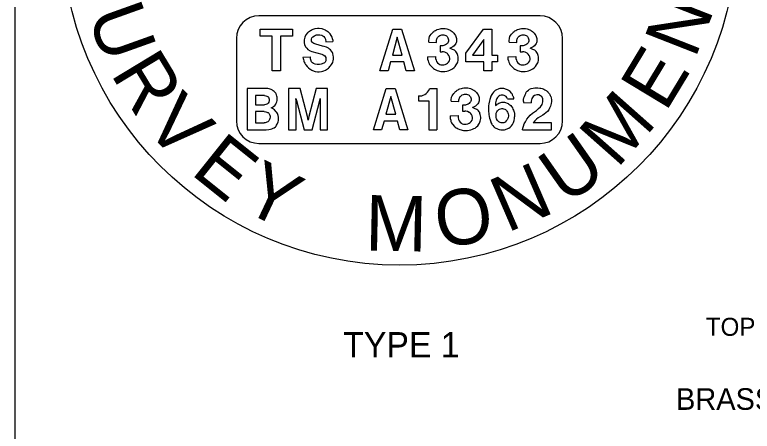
# Model space of a CAD drawing. Extents: x 99862 to 103151, y 100000 to 102076.
# Drawn here: x 99862 to 100680, y 101141 to 101603 of the extents above; entities that cross this region are included whole.
import ezdxf

# ---------------------------------------------------------------- set-up
doc = ezdxf.new("R2010")
doc.units = 0
for name, color, linetype in [('Level 1', 7, 'Continuous'), ('Level 10', 7, 'Continuous'), ('Level 13', 7, 'Continuous'), ('Level 20', 7, 'Continuous'), ('Level 6', 7, 'Continuous')]:
    doc.layers.add(name, color=color, linetype=linetype)

msp = doc.modelspace()

# ---------------------------------------------------------------- linework, layer by layer
at = {"layer": 'Level 1'}
msp.add_lwpolyline([(99862, 99999.5), (103151, 99999.5), (103151, 102075.5), (99862, 102075.5)], close=True, dxfattribs=at)
at = {"layer": 'Level 13'}
for p, q in [((100469.61, 101484.97), (100469.61, 101576.53)), ((100132.83, 101459.97), (100444.61, 101459.97))]:
    msp.add_line(p, q, dxfattribs=at)
for points in [[(100444.61, 101601.53), (100132.83, 101601.53)], [(100107.83, 101576.53), (100107.83, 101484.97)]]:
    msp.add_lwpolyline(points, dxfattribs=at)
for centre, start, end in [((100132.83, 101576.53), 90, 180), ((100444.61, 101576.53), 0, 90), ((100132.83, 101484.97), 180, 270), ((100444.61, 101484.97), 270, 0)]:
    msp.add_arc(centre, 25, start, end, dxfattribs=at)
at = {"layer": 'Level 20'}
for points in [[(100134.35, 101586.59), (100169.91, 101586.59), (100169.91, 101578.98), (100156.7, 101578.98), (100156.7, 101540.59), (100147.56, 101540.59), (100147.56, 101578.98), (100134.35, 101578.98), (100134.35, 101586.59)], [(100187.89, 101583.69), (100188.9, 101584.42), (100189.92, 101585.14), (100190.6, 101585.51), (100191.95, 101586.23), (100193.98, 101586.96), (100195.33, 101587.31), (100197.71, 101587.67), (100198.38, 101587.67), (100199.74, 101587.67), (100202.45, 101587.31), (100203.47, 101586.96), (100204.48, 101586.59), (100206.17, 101585.87), (100207.53, 101585.14), (100208.2, 101584.78), (100209.22, 101584.06)], [(100266.96, 101540.59), (100281.18, 101586.59), (100291, 101586.59), (100305.22, 101540.59), (100296.08, 101540.59), (100293.71, 101550.37), (100278.81, 101550.37), (100276.11, 101540.59), (100266.96, 101540.59)], [(100321.14, 101572.46), (100321.14, 101573.55), (100321.14, 101574.64), (100321.48, 101576.09), (100321.48, 101576.81), (100322.16, 101578.62), (100322.84, 101579.71), (100323.85, 101581.16), (100324.53, 101581.88), (100325.21, 101582.61), (100325.88, 101583.33), (100326.9, 101584.06), (100327.58, 101584.78), (100328.59, 101585.14), (100329.6, 101585.87), (100330.62, 101586.23), (100332.31, 101586.59), (100333.67, 101586.96), (100335.02, 101587.31), (100336.38, 101587.31), (100338.07, 101587.31), (100339.43, 101587.31), (100341.12, 101586.96), (100342.47, 101586.59), (100344.84, 101585.51), (100345.18, 101585.14), (100346.2, 101584.78), (100347.21, 101584.06), (100347.89, 101583.33), (100348.91, 101582.24), (100349.92, 101581.16), (100350.94, 101579.71), (100351.62, 101577.53), (100351.95, 101576.45), (100351.95, 101575), (100351.95, 101572.83), (100351.62, 101571.74), (100351.28, 101570.65), (100350.6, 101569.57), (100350.26, 101569.2), (100349.25, 101568.12), (100347.89, 101567.03), (100346.53, 101566.31), (100344.51, 101565.58)], [(100362.45, 101550.37), (100362.45, 101560.15), (100382.08, 101586.59), (100391.23, 101586.59), (100391.23, 101557.98), (100397.32, 101557.98), (100397.32, 101550.37), (100391.23, 101550.37), (100391.23, 101540.59), (100382.43, 101540.59), (100382.43, 101550.37), (100362.45, 101550.37)], [(100410.24, 101572.46), (100410.24, 101573.55), (100410.24, 101574.64), (100410.58, 101576.09), (100410.58, 101576.81), (100411.25, 101578.62), (100411.93, 101579.71), (100412.95, 101581.16), (100413.62, 101581.88), (100414.3, 101582.61), (100414.98, 101583.33), (100416, 101584.06), (100416.67, 101584.78), (100417.69, 101585.14), (100418.7, 101585.87), (100419.72, 101586.23), (100421.41, 101586.59), (100422.76, 101586.96), (100424.12, 101587.31), (100425.47, 101587.31), (100427.16, 101587.31), (100428.52, 101587.31), (100430.21, 101586.96), (100431.57, 101586.59), (100433.94, 101585.51), (100434.28, 101585.14), (100435.3, 101584.78), (100436.31, 101584.06), (100436.98, 101583.33), (100438, 101582.24), (100439.02, 101581.16), (100440.03, 101579.71), (100440.71, 101577.53), (100441.05, 101576.45), (100441.05, 101575), (100441.05, 101572.83), (100440.71, 101571.74), (100440.37, 101570.65), (100439.69, 101569.57), (100439.36, 101569.2), (100438.34, 101568.12), (100436.98, 101567.03), (100435.63, 101566.31), (100433.6, 101565.58)], [(100187.89, 101583.69), (100186.53, 101582.61), (100184.84, 101580.43), (100183.82, 101577.9), (100183.15, 101575), (100183.15, 101571.74), (100183.49, 101569.57), (100184.51, 101567.03), (100185.86, 101565.58), (100187.21, 101564.14), (100189.58, 101562.69), (100191.61, 101561.96), (100202.45, 101559.06), (100204.14, 101558.33), (100205.83, 101557.25)], [(100191.27, 101573.55), (100191.27, 101575.73), (100191.61, 101577.17), (100192.63, 101578.26), (100194.32, 101579.35), (100195.68, 101580.07), (100196.69, 101580.43), (100198.38, 101580.43), (100200.42, 101580.43), (100202.45, 101580.07), (100203.8, 101579.35), (100204.82, 101578.62), (100205.83, 101577.17), (100206.51, 101575.73), (100206.85, 101572.83)], [(100214.64, 101575), (100213.62, 101578.62), (100212.95, 101579.71), (100211.93, 101581.52), (100210.91, 101582.61), (100209.22, 101584.06)], [(100329.6, 101572.1), (100329.6, 101573.91), (100329.95, 101575), (100330.29, 101575.73), (100330.62, 101576.81), (100330.96, 101577.53), (100331.64, 101578.26), (100332.31, 101578.98), (100333.33, 101579.71), (100334.69, 101580.07), (100335.7, 101580.43), (100337.06, 101580.43), (100338.07, 101580.43), (100339.09, 101580.07), (100340.1, 101579.71), (100340.78, 101579.35), (100341.46, 101578.62), (100342.13, 101577.9), (100342.47, 101577.17), (100342.81, 101576.09), (100343.15, 101575), (100343.15, 101573.55), (100342.81, 101572.46), (100342.47, 101571.74), (100341.8, 101571.01), (100340.78, 101569.93), (100339.77, 101569.2), (100338.75, 101568.85), (100337.73, 101568.48), (100336.72, 101568.12), (100336.04, 101568.12)], [(100418.7, 101572.1), (100418.7, 101573.91), (100419.04, 101575), (100419.38, 101575.73), (100419.72, 101576.81), (100420.05, 101577.53), (100420.73, 101578.26), (100421.41, 101578.98), (100422.43, 101579.71), (100423.78, 101580.07), (100424.8, 101580.43), (100426.15, 101580.43), (100427.16, 101580.43), (100428.18, 101580.07), (100429.2, 101579.71), (100429.87, 101579.35), (100430.55, 101578.62), (100431.23, 101577.9), (100431.57, 101577.17), (100431.9, 101576.09), (100432.25, 101575), (100432.25, 101573.55), (100431.9, 101572.46), (100431.57, 101571.74), (100430.89, 101571.01), (100429.87, 101569.93), (100428.86, 101569.2), (100427.84, 101568.85), (100426.83, 101568.48), (100425.81, 101568.12), (100425.14, 101568.12)], [(100214.64, 101549.65), (100214.98, 101550.01), (100215.31, 101551.46), (100215.65, 101553.27), (100215.65, 101555.08), (100215.65, 101556.17), (100215.31, 101557.62), (100214.64, 101559.79), (100214.3, 101560.87), (100213.29, 101562.32), (100212.27, 101563.77), (100211.25, 101564.49), (100209.9, 101565.58), (100207.87, 101566.67), (100205.16, 101567.39), (100203.47, 101567.76), (100196.02, 101569.93), (100193.64, 101571.01), (100192.63, 101571.74), (100191.95, 101572.46), (100191.27, 101573.55)], [(100206.85, 101572.83), (100214.98, 101573.19)], [(100214.64, 101575), (100214.98, 101573.19)], [(100286.26, 101577.9), (100280.84, 101557.98), (100291.68, 101557.98), (100286.26, 101577.9)], [(100321.14, 101572.46), (100329.6, 101572.1)], [(100382.43, 101575.36), (100369.56, 101557.98), (100382.43, 101557.98), (100382.43, 101575.36)], [(100410.24, 101572.46), (100418.7, 101572.1)], [(100319.79, 101556.17), (100319.79, 101553.27), (100320.47, 101551.46), (100320.8, 101550.01), (100321.48, 101548.56), (100322.16, 101547.47), (100323.17, 101546.39), (100322.5, 101547.11), (100324.86, 101544.57), (100325.55, 101543.85), (100326.56, 101543.12), (100327.58, 101542.4), (100328.93, 101541.67), (100330.62, 101540.96), (100334.69, 101539.87), (100335.7, 101539.87), (100337.39, 101539.87), (100339.09, 101539.87), (100341.12, 101540.23), (100342.81, 101540.59), (100344.51, 101541.31), (100346.2, 101542.04), (100347.56, 101542.76), (100349.25, 101544.21), (100350.6, 101545.3), (100351.62, 101547.11), (100352.29, 101548.2), (100352.97, 101549.28), (100353.31, 101550.37), (100353.64, 101551.82), (100353.99, 101553.27), (100353.99, 101554.72), (100353.64, 101556.17), (100353.31, 101557.62), (100352.97, 101558.7), (100352.63, 101559.79), (100351.95, 101560.87), (100351.28, 101561.96), (100350.6, 101562.69), (100349.58, 101563.41), (100348.57, 101563.77), (100347.56, 101564.14), (100346.2, 101564.86), (100344.51, 101565.58)], [(100328.59, 101556.53), (100328.59, 101554.35), (100329.27, 101552.18), (100329.95, 101550.73), (100330.96, 101549.28), (100332.31, 101548.2), (100333.33, 101547.47), (100334.69, 101547.11), (100336.38, 101547.11), (100337.73, 101547.11), (100339.43, 101547.47), (100340.78, 101548.2), (100342.13, 101548.92), (100343.15, 101550.01), (100344.16, 101551.46), (100344.51, 101552.9), (100344.51, 101554.35), (100344.16, 101556.17), (100343.49, 101557.62), (100342.47, 101559.06), (100341.8, 101559.79), (100341.12, 101560.15), (100339.09, 101561.24), (100337.39, 101561.6), (100336.04, 101561.6)], [(100336.04, 101568.12), (100333.67, 101568.12), (100333.67, 101561.6), (100336.04, 101561.6)], [(100408.88, 101556.17), (100408.88, 101553.27), (100409.56, 101551.46), (100409.9, 101550.01), (100410.58, 101548.56), (100411.25, 101547.47), (100412.27, 101546.39), (100411.59, 101547.11), (100413.96, 101544.57), (100414.64, 101543.85), (100415.65, 101543.12), (100416.67, 101542.4), (100418.03, 101541.67), (100419.72, 101540.96), (100423.78, 101539.87), (100424.8, 101539.87), (100426.49, 101539.87), (100428.18, 101539.87), (100430.21, 101540.23), (100431.9, 101540.59), (100433.6, 101541.31), (100435.3, 101542.04), (100436.65, 101542.76), (100438.34, 101544.21), (100439.69, 101545.3), (100440.71, 101547.11), (100441.38, 101548.2), (100442.07, 101549.28), (100442.4, 101550.37), (100442.74, 101551.82), (100443.08, 101553.27), (100443.08, 101554.72), (100442.74, 101556.17), (100442.4, 101557.62), (100442.07, 101558.7), (100441.73, 101559.79), (100441.05, 101560.87), (100440.37, 101561.96), (100439.69, 101562.69), (100438.68, 101563.41), (100437.66, 101563.77), (100436.65, 101564.14), (100435.3, 101564.86), (100433.6, 101565.58)], [(100417.69, 101556.53), (100417.69, 101554.35), (100418.36, 101552.18), (100419.04, 101550.73), (100420.05, 101549.28), (100421.41, 101548.2), (100422.43, 101547.47), (100423.78, 101547.11), (100425.47, 101547.11), (100426.83, 101547.11), (100428.52, 101547.47), (100429.87, 101548.2), (100431.23, 101548.92), (100432.25, 101550.01), (100433.26, 101551.46), (100433.6, 101552.9), (100433.6, 101554.35), (100433.26, 101556.17), (100432.58, 101557.62), (100431.57, 101559.06), (100430.89, 101559.79), (100430.21, 101560.15), (100428.18, 101561.24), (100426.49, 101561.6), (100425.14, 101561.6)], [(100425.14, 101568.12), (100422.76, 101568.12), (100422.76, 101561.6), (100425.14, 101561.6)], [(100181.46, 101555.8), (100189.92, 101556.17)], [(100181.46, 101555.8), (100181.8, 101554.35), (100182.13, 101552.9), (100182.47, 101551.46), (100182.81, 101550.73), (100183.15, 101550.01), (100183.82, 101548.92), (100184.51, 101547.47), (100184.84, 101547.11), (100186.2, 101545.3), (100187.89, 101543.85), (100189.58, 101542.4), (100190.26, 101542.04), (100191.61, 101541.31), (100192.29, 101540.96), (100193.31, 101540.59), (100193.98, 101540.23), (100195.33, 101539.87), (100197.71, 101539.51), (100198.73, 101539.51), (100199.74, 101539.51), (100202.11, 101539.87), (100203.8, 101540.23), (100204.82, 101540.59), (100206.51, 101541.31), (100207.87, 101542.04), (100208.88, 101542.76), (100209.9, 101543.49), (100210.58, 101544.21), (100211.59, 101545.3), (100212.27, 101546.02), (100213.29, 101547.47), (100213.96, 101548.56), (100214.64, 101549.65)], [(100203.12, 101548.2), (100201.77, 101547.83), (100200.08, 101547.47), (100198.38, 101547.47), (100197.37, 101547.47), (100195.33, 101547.83), (100193.31, 101548.56), (100192.29, 101549.28), (100191.27, 101550.37), (100190.6, 101551.46), (100190.26, 101552.54), (100189.92, 101553.99), (100189.92, 101556.17)], [(100205.83, 101557.25), (100206.85, 101555.44), (100206.85, 101551.46), (100206.17, 101550.01), (100205.5, 101549.28), (100203.12, 101548.2)], [(100319.79, 101556.17), (100328.59, 101556.53)], [(100408.88, 101556.17), (100417.69, 101556.53)], [(100140.94, 101520.92), (100119.95, 101520.92), (100119.95, 101474.92), (100139.58, 101474.92)], [(100139.58, 101474.92), (100140.94, 101474.92), (100143.99, 101475.28), (100145.68, 101475.64), (100147.03, 101476), (100148.05, 101476.37), (100148.73, 101476.73), (100149.74, 101477.45), (100151.1, 101478.54), (100151.78, 101479.26), (100152.45, 101480.35), (100153.13, 101481.43), (100153.47, 101482.16), (100154.14, 101483.97), (100154.48, 101485.42), (100154.48, 101486.15), (100154.48, 101489.04), (100154.14, 101490.86), (100153.8, 101491.94), (100153.47, 101493.03), (100152.79, 101494.11), (100152.11, 101495.2), (100150.08, 101497.37), (100149.07, 101498.1), (100148.05, 101498.82), (100147.37, 101499.18), (100146.36, 101499.54), (100147.37, 101499.91), (100148.05, 101500.27), (100149.07, 101500.99), (100150.42, 101502.08), (100150.76, 101502.44), (100151.44, 101503.53), (100152.11, 101504.62), (100152.79, 101506.07), (100153.13, 101507.52), (100153.13, 101508.24), (100153.13, 101511.13), (100152.79, 101512.58), (100152.45, 101514.03), (100152.11, 101514.76), (100151.78, 101515.12), (100151.44, 101515.85), (100150.42, 101516.93), (100149.74, 101517.65), (100148.73, 101518.38), (100147.71, 101519.1), (100147.03, 101519.47), (100146.36, 101519.83), (100145.34, 101520.19), (100144.32, 101520.55), (100142.63, 101520.92), (100140.94, 101520.92)], [(100165.7, 101520.92), (100165.7, 101474.92), (100174.17, 101474.92), (100174.17, 101506.79), (100173.83, 101509.69), (100174.5, 101507.52), (100182.97, 101474.92), (100191.77, 101474.92), (100200.23, 101507.52), (100200.91, 101509.69), (100200.57, 101506.79), (100200.57, 101474.92), (100209.04, 101474.92), (100209.04, 101520.92), (100196.18, 101520.92), (100188.05, 101489.76), (100187.37, 101485.78), (100186.69, 101489.76), (100178.57, 101520.92), (100165.7, 101520.92)], [(100259.81, 101474.92), (100274.03, 101520.92), (100283.85, 101520.92), (100298.07, 101474.92), (100288.93, 101474.92), (100286.55, 101484.7), (100271.66, 101484.7), (100268.95, 101474.92), (100259.81, 101474.92)], [(100309.63, 101512.95), (100311.33, 101512.95), (100313.35, 101512.95), (100315.05, 101513.67), (100316.74, 101514.4), (100318.44, 101515.49), (100319.79, 101516.93), (100320.8, 101518.38), (100322.5, 101520.92)], [(100322.5, 101520.92), (100330.62, 101520.92)], [(100330.62, 101474.92), (100330.62, 101520.92)], [(100346.19, 101506.79), (100346.19, 101507.88), (100346.19, 101508.97), (100346.53, 101510.42), (100346.53, 101511.13), (100347.2, 101512.95), (100347.89, 101514.03), (100348.9, 101515.49), (100349.58, 101516.21), (100350.25, 101516.93), (100350.93, 101517.65), (100351.95, 101518.38), (100352.63, 101519.1), (100353.64, 101519.47), (100354.65, 101520.19), (100355.67, 101520.55), (100357.36, 101520.92), (100358.72, 101521.28), (100360.07, 101521.64), (100361.42, 101521.64), (100363.12, 101521.64), (100364.47, 101521.64), (100366.17, 101521.28), (100367.52, 101520.92), (100369.89, 101519.83), (100370.23, 101519.47), (100371.25, 101519.1), (100372.26, 101518.38), (100372.94, 101517.65), (100373.96, 101516.57), (100374.97, 101515.49), (100375.99, 101514.03), (100376.67, 101511.86), (100377, 101510.78), (100377, 101509.33), (100377, 101507.15), (100376.67, 101506.07), (100376.33, 101504.97), (100375.65, 101503.89), (100375.31, 101503.53), (100374.3, 101502.44), (100372.94, 101501.36), (100371.58, 101500.63), (100369.56, 101499.91)], [(100415.6, 101509.33), (100415.6, 101510.42), (100415.27, 101511.5), (100414.93, 101512.22), (100414.25, 101513.67), (100413.91, 101514.4), (100413.57, 101515.12), (100412.9, 101515.85), (100411.54, 101517.65), (100410.52, 101518.38), (100409.85, 101518.74), (100408.49, 101519.47), (100407.48, 101519.83), (100406.46, 101520.19), (100405.45, 101520.55), (100404.43, 101520.92), (100403.42, 101520.92), (100402.06, 101520.92), (100401.04, 101520.92), (100400.03, 101520.92), (100399.01, 101520.55), (100398, 101520.19), (100396.3, 101519.47), (100394.95, 101518.74), (100393.6, 101517.65), (100392.92, 101516.93), (100391.91, 101515.49), (100391.22, 101514.4), (100390.21, 101512.58), (100389.2, 101509.69), (100388.86, 101508.6), (100388.51, 101507.15), (100387.84, 101503.89), (100387.5, 101501.72), (100387.5, 101499.91)], [(100426.34, 101506.43), (100426.34, 101508.6), (100426.68, 101510.42), (100427.35, 101512.22), (100428.03, 101514.03), (100428.71, 101515.49), (100429.39, 101516.93), (100430.4, 101518.02), (100431.76, 101519.1), (100432.77, 101520.19), (100434.8, 101520.92), (100436.83, 101521.28), (100438.87, 101521.64), (100440.56, 101521.64), (100442.25, 101521.64), (100444.28, 101521.28), (100445.64, 101521.28), (100446.99, 101520.92), (100448.01, 101520.55), (100448.69, 101520.19), (100450.04, 101519.47), (100450.72, 101519.1), (100451.39, 101518.74), (100451.74, 101518.38), (100452.41, 101518.02), (100452.75, 101517.65), (100453.09, 101517.29), (100453.42, 101516.93), (100453.76, 101516.57), (100454.1, 101516.21), (100454.44, 101515.85), (100455.12, 101515.12), (100455.46, 101514.4), (100455.8, 101513.31), (100456.13, 101512.58), (100456.47, 101511.86), (100456.81, 101510.42), (100457.15, 101508.24), (100457.15, 101506.43), (100456.81, 101504.26)], [(100138.91, 101513.31), (100129.09, 101513.31), (100129.09, 101502.81), (100138.91, 101502.81)], [(100138.91, 101513.31), (100140.6, 101512.95), (100141.62, 101512.58), (100142.29, 101512.22), (100142.63, 101511.86), (100143.31, 101511.13), (100143.99, 101510.05), (100144.32, 101508.97), (100144.32, 101507.52), (100143.65, 101505.7), (100142.97, 101504.62), (100142.29, 101503.89), (100141.62, 101503.53), (100140.6, 101503.17), (100138.91, 101502.81)], [(100309.63, 101512.95), (100309.63, 101507.15), (100321.14, 101507.15), (100321.14, 101474.92), (100330.29, 101474.92)], [(100354.65, 101506.43), (100354.65, 101508.24), (100354.99, 101509.33), (100355.34, 101510.05), (100355.67, 101511.13), (100356.01, 101511.86), (100356.69, 101512.58), (100357.36, 101513.31), (100358.38, 101514.03), (100359.74, 101514.4), (100360.75, 101514.76), (100362.11, 101514.76), (100363.12, 101514.76), (100364.14, 101514.4), (100365.15, 101514.03), (100365.83, 101513.67), (100366.51, 101512.95), (100367.18, 101512.22), (100367.52, 101511.5), (100367.86, 101510.42), (100368.2, 101509.33), (100368.2, 101507.88), (100367.86, 101506.79), (100367.52, 101506.07), (100366.85, 101505.34), (100365.83, 101504.26), (100364.82, 101503.53), (100363.8, 101503.17), (100362.78, 101502.81), (100361.77, 101502.44), (100361.09, 101502.44)], [(100408.49, 101509.33), (100408.16, 101510.05), (100407.82, 101510.78), (100407.14, 101511.86), (100406.46, 101512.58), (100404.77, 101513.31), (100403.76, 101513.67), (100402.73, 101513.67), (100401.38, 101513.67), (100400.03, 101513.31), (100399.01, 101512.58), (100398, 101511.5), (100397.32, 101510.78), (100396.65, 101509.69), (100395.97, 101507.88), (100395.63, 101506.43), (100395.29, 101504.97), (100395.29, 101503.53), (100395.29, 101502.08), (100396.65, 101503.17), (100396.98, 101503.53), (100397.66, 101503.89), (100399.01, 101504.62), (100400.03, 101504.97), (100401.04, 101505.34), (100402.4, 101505.7), (100403.76, 101505.7), (100405.11, 101505.7), (100406.46, 101505.34), (100408.16, 101504.62), (100409.17, 101504.26), (100410.19, 101503.53), (100411.2, 101502.81), (100412.22, 101502.08), (100412.9, 101500.99), (100413.91, 101499.54), (100414.59, 101498.1), (100415.27, 101497.01), (100415.94, 101494.84), (100416.28, 101493.75), (100416.28, 101491.94), (100416.28, 101491.58), (100416.28, 101489.4)], [(100425.32, 101474.92), (100425.66, 101477.09), (100426.34, 101479.26), (100427.02, 101481.8), (100428.37, 101483.97), (100430.06, 101486.87), (100431.76, 101489.04), (100433.79, 101491.21), (100436.16, 101493.39), (100438.53, 101495.2), (100440.56, 101496.65), (100442.93, 101498.82), (100445.3, 101500.63), (100446.99, 101503.17), (100447.67, 101506.07), (100447.67, 101509.33), (100446.65, 101511.86), (100444.96, 101512.95), (100443.27, 101514.03), (100440.9, 101514.03), (100438.53, 101513.31), (100436.83, 101512.22), (100435.48, 101509.69), (100434.8, 101506.79), (100434.8, 101504.97)], [(100279.11, 101512.22), (100273.68, 101492.31), (100284.52, 101492.31), (100279.11, 101512.22)], [(100346.19, 101506.79), (100354.65, 101506.43)], [(100408.49, 101509.33), (100415.6, 101509.33)], [(100426.34, 101506.43), (100426.34, 101505.34)], [(100426.34, 101505.34), (100434.8, 101504.97)], [(100344.84, 101490.49), (100344.84, 101487.6), (100345.51, 101485.78), (100345.85, 101484.33), (100346.53, 101482.88), (100347.2, 101481.8), (100348.22, 101480.71), (100347.55, 101481.43), (100349.91, 101478.9), (100350.6, 101478.18), (100351.61, 101477.45), (100352.63, 101476.73), (100353.98, 101476), (100355.67, 101475.28), (100359.74, 101474.19), (100360.75, 101474.19), (100362.44, 101474.19), (100364.14, 101474.19), (100366.17, 101474.55), (100367.86, 101474.92), (100369.56, 101475.64), (100371.25, 101476.37), (100372.6, 101477.09), (100374.3, 101478.54), (100375.65, 101479.63), (100376.67, 101481.43), (100377.34, 101482.53), (100378.02, 101483.61), (100378.36, 101484.7), (100378.69, 101486.15), (100379.04, 101487.6), (100379.04, 101489.04), (100378.69, 101490.49), (100378.36, 101491.94), (100378.02, 101493.03), (100377.68, 101494.11), (100377, 101495.2), (100376.33, 101496.29), (100375.65, 101497.01), (100374.63, 101497.74), (100373.62, 101498.1), (100372.6, 101498.46), (100371.25, 101499.18), (100369.56, 101499.91)], [(100361.09, 101502.44), (100358.72, 101502.44), (100358.72, 101495.92), (100361.09, 101495.92)], [(100387.5, 101499.91), (100387.5, 101498.1), (100387.5, 101495.92), (100387.84, 101492.66), (100387.84, 101491.94), (100388.18, 101489.76), (100388.51, 101487.96), (100389.2, 101486.15), (100389.87, 101483.97), (100390.21, 101483.25), (100391.22, 101481.43), (100391.56, 101480.71), (100392.24, 101479.99), (100393.26, 101478.54), (100394.27, 101477.81), (100395.63, 101477.09), (100396.65, 101476.37), (100398.34, 101475.64), (100399.35, 101475.28), (100401.04, 101474.92), (100402.73, 101474.92), (100405.11, 101474.92), (100406.46, 101475.28), (100408.83, 101476.37), (100410.19, 101477.09), (100411.54, 101478.18), (100412.9, 101479.63), (100414.25, 101481.08), (100415.27, 101483.25), (100415.94, 101485.42), (100416.28, 101487.6), (100416.28, 101489.4)], [(100395.97, 101490.13), (100395.97, 101491.94), (100395.97, 101493.39), (100396.3, 101494.47), (100396.65, 101495.2), (100397.32, 101496.29), (100397.66, 101496.65), (100398.67, 101497.37), (100399.01, 101497.74), (100399.69, 101498.1), (100402.06, 101498.82), (100403.08, 101498.82), (100404.09, 101498.46), (100405.45, 101498.1), (100406.46, 101497.74), (100407.48, 101496.65), (100407.82, 101495.92), (100408.49, 101494.84), (100408.83, 101493.75), (100409.17, 101492.66), (100409.51, 101491.21), (100409.51, 101490.13), (100409.17, 101488.68), (100408.83, 101487.6), (100408.16, 101486.15), (100407.48, 101485.42), (100406.8, 101484.7), (100407.14, 101485.06), (100405.78, 101483.61), (100404.43, 101482.88), (100403.08, 101482.88), (100401.38, 101482.88), (100400.37, 101483.25), (100399.01, 101483.97), (100398.67, 101484.33), (100397.32, 101485.42), (100396.3, 101487.23), (100395.97, 101488.68), (100395.97, 101490.13)], [(100456.81, 101504.26), (100456.13, 101501.36), (100455.12, 101499.18), (100454.44, 101497.37), (100452.75, 101495.56), (100451.05, 101493.75), (100449.36, 101492.31), (100447.67, 101491.21), (100444.96, 101489.76), (100442.59, 101488.31), (100440.56, 101486.87), (100438.87, 101485.06), (100437.17, 101482.88)], [(100138.57, 101495.56), (100129.09, 101495.56), (100129.09, 101482.88), (100138.57, 101482.88)], [(100138.57, 101495.56), (100140.6, 101495.2), (100141.62, 101494.84), (100142.29, 101494.47), (100142.97, 101494.11), (100143.65, 101493.39), (100144.32, 101492.66), (100144.67, 101491.94), (100145, 101491.21), (100145.34, 101490.13), (100145.34, 101489.04), (100145, 101487.6), (100144.67, 101486.51), (100144.32, 101485.78), (100143.65, 101485.06), (100143.31, 101484.7), (100142.63, 101483.97), (100141.62, 101483.61), (100140.94, 101483.25), (100139.58, 101482.88), (100138.57, 101482.88)], [(100344.84, 101490.49), (100353.64, 101490.86)], [(100353.64, 101490.86), (100353.64, 101488.68), (100354.32, 101486.51), (100354.99, 101485.06), (100356.01, 101483.61), (100357.36, 101482.53), (100358.38, 101481.8), (100359.74, 101481.43), (100361.42, 101481.43), (100362.78, 101481.43), (100364.47, 101481.8), (100365.83, 101482.53), (100367.18, 101483.25), (100368.2, 101484.33), (100369.21, 101485.78), (100369.56, 101487.23), (100369.56, 101488.68), (100369.21, 101490.49), (100368.54, 101491.94), (100367.52, 101493.39), (100366.85, 101494.11), (100366.17, 101494.47), (100364.14, 101495.56), (100362.44, 101495.92), (100361.09, 101495.92)], [(100425.32, 101474.92), (100457.49, 101474.92), (100457.49, 101482.88), (100437.17, 101482.88)]]:
    msp.add_lwpolyline(points, dxfattribs=at)
at = {"layer": 'Level 6'}
msp.add_circle((100288.72, 101700), 375, dxfattribs=at)

# ---------------------------------------------------------------- texts
at = {"layer": 'Level 10'}
for s, rotation, p in [('N', 68.59815, (100616.46, 101553.05)), ('U', 289.66641, (99942.4, 101602.45)), ('R', 301.20479, (99967.72, 101537.48)), ('E', 58.82128, (100583.82, 101493.7)), ('V', 314.61462, (100004.09, 101477.67)), ('M', 48.48341, (100530.01, 101431.32)), ('U', 35.07358, (100472.85, 101390.93)), ('E', 321.31953, (100055.89, 101426.84)), ('Y', 334.72936, (100110.87, 101387.23)), ('N', 23.40658, (100407.97, 101360.51)), ('O', 8.25393, (100332.38, 101343.82)), ('M', 358.80062, (100250.21, 101341.35))]:
    msp.add_text(s, height=61.5, rotation=rotation, dxfattribs=at).set_placement(p)
at = {"layer": 'Level 20'}
for s, height, p in [('TOP VIEW', 20, (100628.52, 101246.57)), ('TYPE 1', 28, (100226.38, 101222.69)), ('BRASS DISC', 24, (100595.5, 101164.46))]:
    msp.add_text(s, height=height, dxfattribs=at).set_placement(p)

doc.saveas('drawing.dxf')
